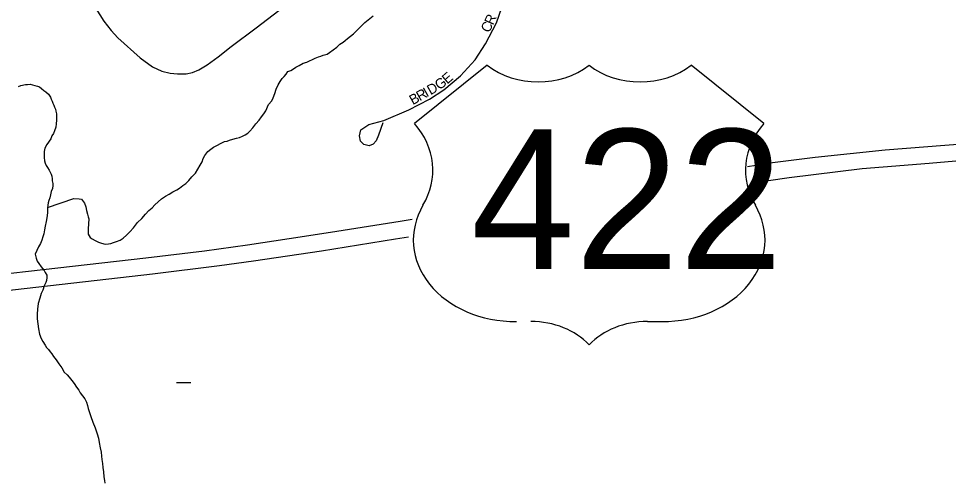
# Model space of a CAD drawing. Extents: x -10.1 to 68, y -9.5 to 29.2.
# Drawn here: x 2.607 to 3.483, y 18.982 to 19.418 of the extents above; entities that cross this region are included whole.
import ezdxf

# ---------------------------------------------------------------- set-up
doc = ezdxf.new("R2010")
doc.units = 0
for name, color, linetype in [('GM_X_Minor_River', 7, 'Continuous'), ('GM_X_Township_Subdivision', 7, 'Continuous'), ('GM_X_Township_Subdivision_Text', 7, 'Continuous'), ('GM_X_US_Route', 7, 'Continuous'), ('GM_X_US_Shield', 7, 'Continuous')]:
    doc.layers.add(name, color=color, linetype=linetype)

msp = doc.modelspace()

# ---------------------------------------------------------------- linework, layer by layer
at = {"layer": 'GM_X_Minor_River'}
for points in [[(2.91447, 19.39748), (2.91672, 19.39942), (2.91973, 19.40137), (2.92235, 19.40369), (2.93318, 19.41452), (2.93768, 19.41801), (2.94105, 19.42073)], [(2.6338, 19.23986), (2.6587, 19.24841), (2.66364, 19.24811), (2.66592, 19.24776), (2.66864, 19.24401), (2.66984, 19.2406), (2.67066, 19.2372), (2.67147, 19.23379), (2.67228, 19.23114), (2.67269, 19.22924), (2.67209, 19.21973), (2.67213, 19.21744), (2.67217, 19.21479), (2.67412, 19.21177), (2.67605, 19.21029), (2.67873, 19.20881), (2.68179, 19.20734), (2.68485, 19.20625), (2.68828, 19.20554), (2.69132, 19.20559), (2.69359, 19.20601), (2.69623, 19.20681), (2.69887, 19.208), (2.70227, 19.20919), (2.70528, 19.21114), (2.70827, 19.21385), (2.71164, 19.21695), (2.71499, 19.22081), (2.7187, 19.22581), (2.72282, 19.22968), (2.72617, 19.23354), (2.72953, 19.23702), (2.73252, 19.23973), (2.73514, 19.24243), (2.73813, 19.24515), (2.7415, 19.24824), (2.74526, 19.25058), (2.74864, 19.25254), (2.75202, 19.25488), (2.75579, 19.25646), (2.75843, 19.25803), (2.76142, 19.26074), (2.76442, 19.26269), (2.76704, 19.26539), (2.77002, 19.26886), (2.77338, 19.27234), (2.77559, 19.27618), (2.77781, 19.28002), (2.77966, 19.28309), (2.78074, 19.28615), (2.78222, 19.28884), (2.78519, 19.29269), (2.78781, 19.29501), (2.79044, 19.29696), (2.80061, 19.30207), (2.80326, 19.30249), (2.80552, 19.30329), (2.80854, 19.30448), (2.81195, 19.30529), (2.81497, 19.30611), (2.81761, 19.30729), (2.82025, 19.30847), (2.82288, 19.31004), (2.82475, 19.31197), (2.82736, 19.31505), (2.83033, 19.31891), (2.83331, 19.32238), (2.83554, 19.32546), (2.83777, 19.32815), (2.83962, 19.33123), (2.84218, 19.33697), (2.84554, 19.34045), (2.84663, 19.34351), (2.84809, 19.34734), (2.84953, 19.35154), (2.85136, 19.35576), (2.85321, 19.35883), (2.85506, 19.36152), (2.85693, 19.36345), (2.85879, 19.36576), (2.86065, 19.36808), (2.86329, 19.36926), (2.86592, 19.37083), (2.86818, 19.37238), (2.87119, 19.37395), (2.87495, 19.37592), (2.87835, 19.37711), (2.88099, 19.3783), (2.88363, 19.37948), (2.88627, 19.38067), (2.88929, 19.38186), (2.89156, 19.38265), (2.89382, 19.38345), (2.8976, 19.38465), (2.89985, 19.38621), (2.90323, 19.38855), (2.9066, 19.39126), (2.9096, 19.39398), (2.9126, 19.39593), (2.91447, 19.39748)], [(2.60642, 19.35403), (2.60868, 19.35483), (2.61322, 19.35604), (2.61512, 19.35607), (2.61739, 19.35611), (2.61968, 19.35576), (2.62197, 19.35504), (2.62426, 19.35432), (2.62617, 19.35359), (2.6281, 19.3521), (2.63041, 19.35024), (2.63232, 19.34913), (2.63464, 19.34688), (2.63659, 19.34387), (2.63738, 19.34199), (2.63817, 19.3401), (2.63896, 19.33821), (2.63976, 19.33632), (2.64055, 19.33443), (2.64134, 19.33254), (2.64175, 19.33065), (2.64217, 19.32837), (2.64221, 19.32571), (2.64227, 19.32229), (2.64195, 19.31886), (2.64162, 19.31582), (2.64053, 19.31238), (2.63944, 19.30969), (2.63796, 19.30739), (2.63687, 19.30471), (2.63316, 19.29933), (2.63132, 19.29587), (2.63061, 19.29282), (2.63065, 19.29016), (2.6307, 19.28712), (2.63113, 19.28408), (2.63155, 19.28181), (2.63273, 19.27954), (2.6339, 19.27766), (2.63546, 19.27503), (2.63742, 19.27126), (2.63784, 19.26936), (2.63825, 19.26709), (2.63829, 19.26519), (2.63871, 19.26253), (2.63874, 19.26063), (2.63841, 19.25796), (2.63732, 19.2549), (2.63661, 19.25185), (2.63589, 19.24918), (2.63518, 19.2465), (2.63446, 19.24421), (2.63411, 19.2423), (2.63377, 19.23963), (2.63381, 19.23773), (2.63385, 19.23507), (2.63317, 19.23012), (2.63247, 19.22668), (2.63178, 19.22249), (2.63108, 19.21905), (2.63038, 19.21524), (2.6293, 19.21218), (2.62859, 19.20913), (2.62712, 19.20606), (2.62527, 19.20299), (2.62235, 19.1961), (2.62317, 19.19231), (2.62398, 19.18928), (2.62554, 19.18702), (2.62787, 19.18402), (2.63059, 19.18064), (2.63176, 19.17876), (2.63332, 19.17612), (2.63336, 19.17384), (2.63302, 19.17117), (2.63229, 19.16926), (2.63083, 19.16619), (2.62938, 19.16199), (2.62791, 19.15892), (2.62647, 19.15433), (2.62503, 19.14937), (2.62436, 19.14403), (2.62406, 19.13947)], [(2.62406, 19.13947), (2.62413, 19.1349), (2.62459, 19.13035), (2.62543, 19.12542), (2.62627, 19.12049), (2.62786, 19.11633), (2.62943, 19.11369), (2.63176, 19.11031), (2.63294, 19.10805), (2.63487, 19.10618), (2.63643, 19.10392), (2.63798, 19.10204), (2.63954, 19.09941), (2.64187, 19.0964), (2.64459, 19.09265), (2.64731, 19.08889), (2.64966, 19.08474), (2.65236, 19.08213), (2.6543, 19.07988), (2.65663, 19.07687), (2.65896, 19.07387), (2.66129, 19.07048), (2.66324, 19.06785), (2.6648, 19.06522), (2.66907, 19.05958), (2.67064, 19.05657), (2.67146, 19.05316), (2.67226, 19.05051), (2.67307, 19.04748), (2.67467, 19.04294), (2.67665, 19.03765), (2.67864, 19.03236), (2.68063, 19.02669), (2.68185, 19.02253), (2.68267, 19.01836), (2.68352, 19.01343), (2.68435, 19.00926), (2.68479, 19.00546), (2.68522, 19.00243), (2.68566, 18.99863), (2.68611, 18.99484), (2.68656, 18.99066), (2.68701, 18.98611), (2.68745, 18.98269), (2.68787, 18.98004)]]:
    msp.add_lwpolyline(points, dxfattribs=at)
at = {"layer": 'GM_X_Township_Subdivision'}
for points in [[(2.95012, 19.31986), (2.94611, 19.3083), (2.94376, 19.30288), (2.94092, 19.29981), (2.93715, 19.29816), (2.9322, 19.29934), (2.92889, 19.30264), (2.92795, 19.30759), (2.92936, 19.31326), (2.93691, 19.31821), (2.95107, 19.32198), (2.97466, 19.33213), (2.99424, 19.34204), (3.00769, 19.35076), (3.02326, 19.36398), (3.03717, 19.37931), (3.04685, 19.39441), (3.05723, 19.41399), (3.06242, 19.42838), (3.06643, 19.44513), (3.06808, 19.4614), (3.06855, 19.47957), (3.06855, 19.51071), (3.06713, 19.56921)], [(2.67954, 19.42767), (2.68709, 19.41564), (2.69393, 19.40691), (2.7003, 19.40007), (2.72129, 19.38096), (2.73285, 19.37247), (2.74158, 19.36846), (2.7496, 19.36657), (2.75644, 19.36586), (2.7647, 19.3661), (2.7706, 19.36728), (2.7765, 19.36964), (2.78428, 19.37435), (2.79466, 19.3819), (2.80716, 19.39181), (2.83052, 19.40927), (2.85741, 19.42979)]]:
    msp.add_lwpolyline(points, dxfattribs=at)
at = {"layer": 'GM_X_US_Route'}
for points in [[(3.29415, 19.27871), (3.31772, 19.28242), (3.3578, 19.28735), (3.42382, 19.29421), (3.50034, 19.30042), (3.62162, 19.31105), (3.63002, 19.31178), (3.7014, 19.318), (3.78093, 19.32507), (3.84652, 19.33064), (3.87631, 19.33343), (4.07094, 19.35058), (4.1121, 19.35444), (4.25507, 19.3673), (4.31187, 19.37244), (4.37511, 19.37694)], [(3.29667, 19.26288), (3.33336, 19.26827), (3.40217, 19.27663), (3.4221, 19.27834), (3.4654, 19.28177), (3.56615, 19.29056), (3.62192, 19.29526), (3.72948, 19.30449), (3.8015, 19.31092), (3.86174, 19.31628), (4.01521, 19.33), (4.10288, 19.33815), (4.14125, 19.34158), (4.19591, 19.34651), (4.29172, 19.35508), (4.35389, 19.36001), (4.39161, 19.36215)], [(2.1, 19.12116), (2.124, 19.12358), (2.14597, 19.12633), (2.15315, 19.12723), (2.29141, 19.14309), (2.48818, 19.16539), (2.72654, 19.19253), (2.78184, 19.19903), (2.82235, 19.20461), (2.86179, 19.21061), (2.9008, 19.21661), (2.96639, 19.22711), (2.9778, 19.22891)], [(2.15121, 19.11125), (2.24067, 19.12154), (2.29033, 19.12701), (2.37093, 19.13601), (2.49332, 19.15016), (2.73275, 19.17738), (2.79599, 19.18532), (2.82814, 19.1896), (2.89223, 19.19925), (2.96189, 19.21039), (2.97445, 19.21233)]]:
    msp.add_lwpolyline(points, dxfattribs=at)
at = {"layer": 'GM_X_US_Shield'}
for p, q in [((3.04855, 19.37413), (2.97988, 19.3192)), ((3.30947, 19.3192), (3.24081, 19.37413)), ((3.19961, 19.13243), (3.21334, 19.13243)), ((2.75538, 19.07487), (2.76912, 19.07487))]:
    msp.add_line(p, q, dxfattribs=at)
for centre, major_axis, start_param, end_param in [((3.09661, 19.41336), (-0.06866, 0), 0.795399, 2.346194), ((3.19274, 19.41336), (-0.06866, 0), 0.795399, 2.346194), ((2.90114, 19.27509), (0.09613, 0), 5.838949, 6.894067), ((3.38822, 19.27509), (-0.09613, 0), 5.672304, 6.727422), ((3.07494, 19.20933), (0.09613, 0), 2.702327, 4.723529), ((3.21441, 19.20933), (-0.09613, 0), 1.559657, 3.580859), ((3.08975, 19.0775), (-0.06866, 0), 3.785094, 4.712389), ((3.19961, 19.0775), (-0.06866, 0), 4.712389, 5.639684)]:
    msp.add_ellipse(centre, major_axis=major_axis, ratio=0.8, start_param=start_param, end_param=end_param, dxfattribs=at)

# ---------------------------------------------------------------- texts
at = {"layer": 'GM_X_Township_Subdivision_Text'}
for s, rotation, p in [('C', 61.90322, (3.05015, 19.40399)), ('R', 66.42545, (3.05404, 19.41134)), ('G', 35.37416, (3.00326, 19.35041)), ('E', 40.91315, (3.01085, 19.35585)), ('D', 29.30298, (2.99507, 19.34575)), ('B', 29.31409, (2.97836, 19.33636)), ('R', 29.28103, (2.98489, 19.34003)), ('I', 29.31828, (2.99144, 19.34371))]:
    msp.add_text(s, height=0.00947, rotation=rotation, dxfattribs=at).set_placement(p)
at = {"layer": 'GM_X_US_Shield'}
msp.add_text('422', height=0.131836, dxfattribs=at).set_placement((3.03324, 19.18187))

doc.saveas('drawing.dxf')
